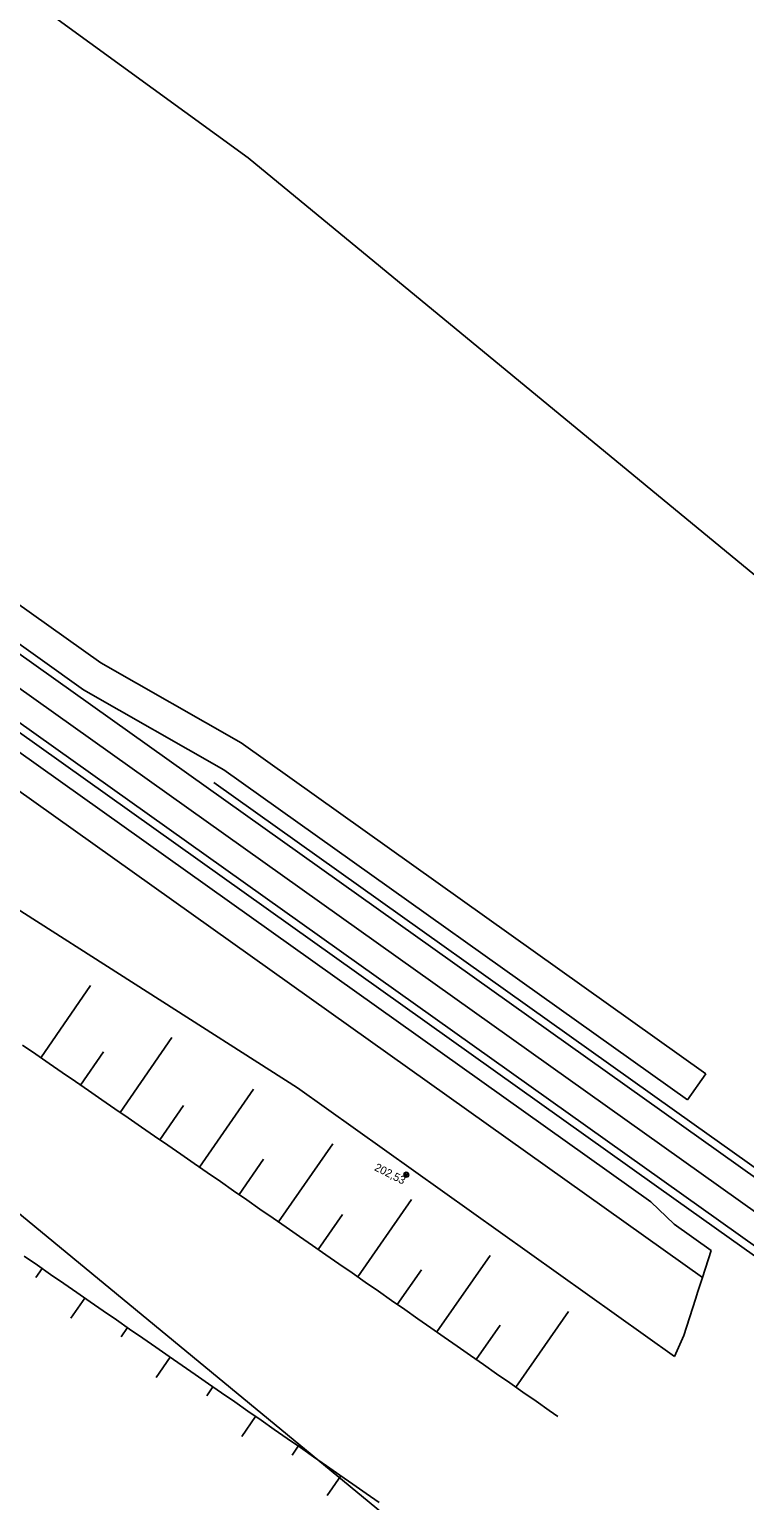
# Model space of a CAD drawing. Extents: x -551750 to -547457, y -1150683 to -1148508.
# Drawn here: x -550183 to -550138.3, y -1149131.6 to -1149039.7 of the extents above; entities that cross this region are included whole.
import ezdxf

# ---------------------------------------------------------------- set-up
doc = ezdxf.new("R2010")
doc.units = 0
for name, color, linetype in [('SO221815_VYSKOPIS', 7, 'Continuous'), ('u_ochranne_pasmo_CD', 7, 'Continuous'), ('u_trat navrh', 7, 'Continuous')]:
    doc.layers.add(name, color=color, linetype=linetype)

# ---------------------------------------------------------------- blocks, each defined once
blk = doc.blocks.new('SO221824_VYSKOPIS')
at = {"layer": 'SO221815_VYSKOPIS'}
for p, q in [((0.123, -0.085), (-0.123, 0.085)), ((0.086, 0.123), (-0.086, -0.123)), ((0.086, 0.123), (0, 0)), ((0, 0), (0.123, -0.085))]:
    blk.add_line(p, q, dxfattribs=at)
blk.add_lwpolyline([(-0.086, -0.123), (0, 0), (-0.123, 0.085)], dxfattribs=at)
blk.add_circle((0, 0), 0.15, dxfattribs=at)
for start, end in [(145.36204, 235.15382), (325.36204, 55.15382)]:
    blk.add_arc((0, 0), 0.15, start, end, dxfattribs=at)

msp = doc.modelspace()

# ---------------------------------------------------------------- linework, layer by layer
at = {"layer": 'u_ochranne_pasmo_CD'}
for points in [[(-551204.608, -1148514.466), (-551167.268, -1148510.525), (-551132.147, -1148508.579), (-551091.632, -1148508.39), (-551057.892, -1148509.373), (-551016.744, -1148513.627), (-550982.17, -1148519.492), (-550943.055, -1148529.955), (-550913.311, -1148538.83), (-550891.178, -1148546.582), (-550830.711, -1148571.434), (-550783.204, -1148596.843), (-550731.358, -1148628.54), (-550577.063, -1148738.919), (-550506.269, -1148793.922), (-550406.245, -1148864.296), (-550262.043, -1148980.172), (-550169.322, -1149047.694), (-550081.54, -1149120.017), (-549998.063, -1149180.267)], [(-551198.31, -1148574.135), (-551162.456, -1148570.351), (-551130.346, -1148568.572), (-551092.366, -1148568.394), (-551061.857, -1148569.283), (-551024.854, -1148573.108), (-550994.968, -1148578.178), (-550959.389, -1148587.695), (-550931.815, -1148595.923), (-550912.514, -1148602.683), (-550895.525, -1148609.665), (-550856.329, -1148625.775), (-550813.026, -1148648.936), (-550764.505, -1148678.6), (-550612.938, -1148787.027), (-550541.958, -1148842.175), (-550442.336, -1148912.265), (-550342.715, -1148992.318), (-550298.516, -1149027.836), (-550206.092, -1149095.142), (-550118.211, -1149167.545), (-550033.177, -1149228.919)]]:
    msp.add_lwpolyline(points, dxfattribs=at)
at = {"layer": 'u_trat navrh'}
for p, q in [((-550179.601, -1149080.918), (-550203.872, -1149063.631)), ((-550178.522, -1149079.231), (-550200.675, -1149063.452)), ((-550204.162, -1149064.038), (-550115.928, -1149126.867)), ((-550205.177, -1149065.464), (-550087.554, -1149149.22)), ((-550206.192, -1149066.889), (-550088.569, -1149150.645)), ((-550144.163, -1149112.9), (-550207.062, -1149068.111)), ((-550140.946, -1149117.646), (-550208.222, -1149069.74)), ((-550166.235, -1149105.784), (-550216.282, -1149073.844)), ((-550178.522, -1149079.231), (-550169.759, -1149084.239)), ((-550179.601, -1149080.918), (-550170.838, -1149085.926)), ((-550169.759, -1149084.239), (-550140.719, -1149104.918)), ((-550170.838, -1149085.926), (-550141.88, -1149106.547)), ((-550182.259, -1149103.909), (-550179.151, -1149099.391)), ((-550177.305, -1149107.322), (-550174.07, -1149102.634)), ((-550179.781, -1149105.615), (-550178.355, -1149103.544)), ((-550140.719, -1149104.918), (-550141.88, -1149106.547)), ((-550172.355, -1149110.742), (-550168.989, -1149105.877)), ((-550142.677, -1149122.563), (-550166.235, -1149105.784)), ((-550174.829, -1149109.031), (-550173.344, -1149106.882)), ((-550167.41, -1149114.168), (-550164.017, -1149109.279)), ((-550169.882, -1149112.454), (-550168.347, -1149110.239)), ((-550162.47, -1149117.601), (-550159.111, -1149112.773)), ((-550164.939, -1149115.884), (-550163.42, -1149113.698)), ((-550157.534, -1149121.04), (-550154.205, -1149116.268)), ((-550182.186, -1149117.075), (-550182.578, -1149117.644)), ((-550160.001, -1149119.32), (-550158.497, -1149117.16)), ((-550179.515, -1149118.921), (-550180.389, -1149120.184)), ((-550152.601, -1149124.484), (-550149.299, -1149119.762)), ((-550176.845, -1149120.768), (-550177.238, -1149121.336)), ((-550155.067, -1149122.761), (-550153.575, -1149120.625)), ((-550174.177, -1149122.618), (-550175.049, -1149123.875)), ((-550171.51, -1149124.469), (-550171.901, -1149125.032)), ((-550168.845, -1149126.322), (-550169.71, -1149127.566)), ((-550166.18, -1149128.177), (-550166.567, -1149128.732)), ((-550163.517, -1149130.034), (-550164.37, -1149131.256))]:
    msp.add_line(p, q, dxfattribs=at)
for points in [[(-550102.809, -1149141.119), (-550132.807, -1149119.759), (-550142.581, -1149112.799), (-550206.482, -1149067.297)], [(-550171.455, -1149086.714), (-550141.458, -1149108.074), (-550131.683, -1149115.035), (-550115.638, -1149126.46)], [(-550183.4, -1149103.125), (-550182.575, -1149103.692), (-550181.75, -1149104.259), (-550180.926, -1149104.827), (-550180.102, -1149105.394), (-550179.277, -1149105.962), (-550178.453, -1149106.53), (-550177.629, -1149107.098), (-550176.806, -1149107.666), (-550175.982, -1149108.235), (-550175.158, -1149108.803), (-550174.335, -1149109.372), (-550173.512, -1149109.941), (-550172.689, -1149110.511), (-550171.866, -1149111.08), (-550171.043, -1149111.65), (-550170.22, -1149112.22), (-550169.398, -1149112.79), (-550168.575, -1149113.36), (-550167.753, -1149113.93), (-550166.931, -1149114.501), (-550166.109, -1149115.071), (-550165.287, -1149115.642), (-550164.465, -1149116.213), (-550163.643, -1149116.784), (-550162.822, -1149117.356), (-550162, -1149117.927), (-550161.179, -1149118.499), (-550160.358, -1149119.071), (-550159.537, -1149119.643), (-550158.716, -1149120.215), (-550157.895, -1149120.788), (-550157.074, -1149121.36), (-550156.254, -1149121.933), (-550155.433, -1149122.505), (-550154.613, -1149123.078), (-550153.793, -1149123.652), (-550152.973, -1149124.225), (-550152.153, -1149124.798), (-550151.333, -1149125.372), (-550150.513, -1149125.945), (-550149.975, -1149126.322)], [(-550142.677, -1149122.563), (-550142.101, -1149121.251), (-550141.382, -1149118.997), (-550141.229, -1149118.521), (-550140.946, -1149117.646), (-550140.402, -1149115.958), (-550142.713, -1149114.311), (-550144.168, -1149112.907), (-550144.163, -1149112.9)], [(-550183.295, -1149116.31), (-550182.472, -1149116.877), (-550181.65, -1149117.445), (-550180.828, -1149118.013), (-550180.006, -1149118.581), (-550179.184, -1149119.15), (-550178.362, -1149119.718), (-550177.54, -1149120.287), (-550176.719, -1149120.856), (-550175.898, -1149121.425), (-550175.076, -1149121.994), (-550174.255, -1149122.564), (-550173.434, -1149123.133), (-550172.613, -1149123.703), (-550171.792, -1149124.273), (-550170.972, -1149124.843), (-550170.151, -1149125.414), (-550169.33, -1149125.984), (-550168.51, -1149126.555), (-550167.69, -1149127.126), (-550166.87, -1149127.697), (-550166.05, -1149128.268), (-550165.23, -1149128.839), (-550164.41, -1149129.411), (-550163.59, -1149129.983), (-550162.771, -1149130.554), (-550161.951, -1149131.126), (-550161.132, -1149131.699)]]:
    msp.add_lwpolyline(points, dxfattribs=at)

# ---------------------------------------------------------------- block references
at = {"layer": 'u_trat navrh', "rotation": -31.851985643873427}
msp.add_blockref('SO221824_VYSKOPIS', (-550159.438, -1149111.214), dxfattribs=at)

# ---------------------------------------------------------------- texts
at = {"layer": 'u_trat navrh'}
msp.add_text('202,53', height=0.5, rotation=333.25678, dxfattribs=at).set_placement((-550161.473, -1149110.919))

doc.saveas('drawing.dxf')
